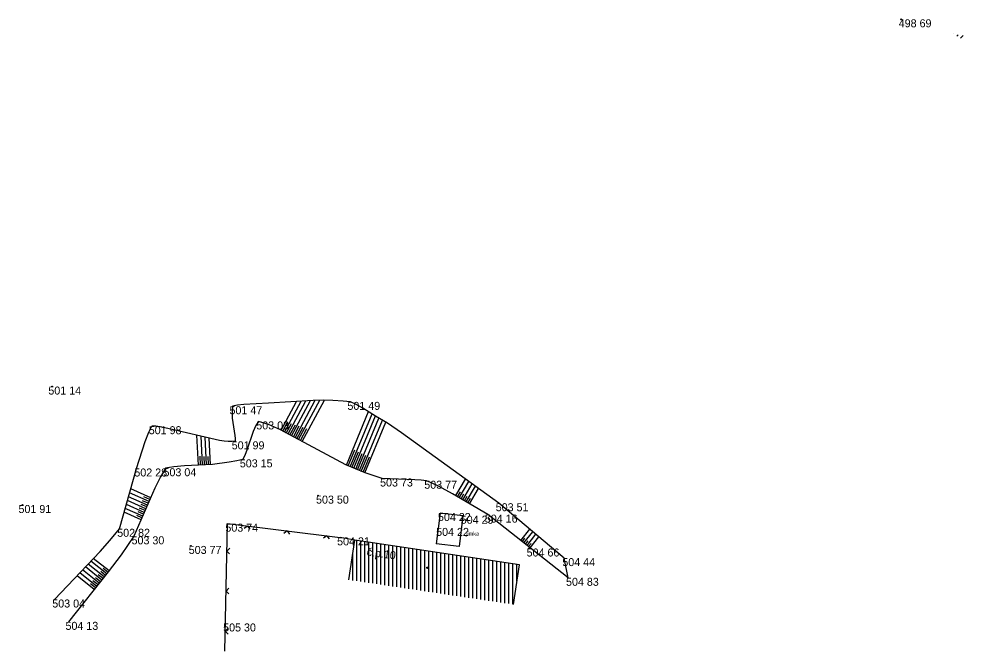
# Model space of a CAD drawing. Extents: x -554123 to -553118, y -1076825 to -1073672.
# Drawn here: x -553382.9 to -553265, y -1076824.9 to -1076745.9 of the extents above; entities that cross this region are included whole.
import ezdxf

# ---------------------------------------------------------------- set-up
doc = ezdxf.new("R2010")
doc.units = 0
for name, color, linetype in [('1', 7, 'Continuous'), ('12', 7, 'Continuous'), ('14', 7, 'Continuous'), ('18', 7, 'Continuous'), ('26', 7, 'Continuous'), ('27', 7, 'Continuous'), ('32', 7, 'Continuous'), ('47', 7, 'Continuous'), ('52', 7, 'Continuous'), ('54', 7, 'Continuous'), ('6', 7, 'Continuous')]:
    doc.layers.add(name, color=color, linetype=linetype)

# ---------------------------------------------------------------- blocks, each defined once
blk = doc.blocks.new('POINT_DISPLAY')
blk.add_line((0, 0), (0, 0))
blk = doc.blocks.new('T')
at = {"layer": '6'}
blk.add_circle((0, 0), 0.05, dxfattribs=at)
blk = doc.blocks.new('BZ')
at = {"layer": '47'}
blk.add_circle((0, 0), 0.0875, dxfattribs=at)

msp = doc.modelspace()

# ---------------------------------------------------------------- linework, layer by layer
at = {"layer": '12'}
for p, q in [((-553357.18, -1076824.88), (-553356.85, -1076808.96)), ((-553356.85, -1076808.96), (-553342.79, -1076810.67)), ((-553354.37, -1076809.26), (-553354.76, -1076809.57)), ((-553354.37, -1076809.26), (-553354.06, -1076809.66)), ((-553349.41, -1076809.86), (-553349.8, -1076810.17)), ((-553349.41, -1076809.86), (-553349.1, -1076810.26)), ((-553344.44, -1076810.47), (-553344.84, -1076810.78)), ((-553344.44, -1076810.47), (-553344.13, -1076810.86)), ((-553340.96, -1076811.02), (-553342.79, -1076810.67)), ((-553356.92, -1076812.38), (-553356.56, -1076812.03)), ((-553356.92, -1076812.38), (-553356.58, -1076812.74)), ((-553357.03, -1076817.38), (-553356.66, -1076817.03)), ((-553357.03, -1076817.38), (-553356.68, -1076817.74)), ((-553357.13, -1076822.38), (-553356.77, -1076822.03)), ((-553357.13, -1076822.38), (-553356.78, -1076822.74))]:
    msp.add_line(p, q, dxfattribs=at)
at = {"layer": '14'}
for p, q in [((-553341.7, -1076815.97), (-553340.96, -1076811.02)), ((-553320.4, -1076814.09), (-553340.96, -1076811.02)), ((-553321.14, -1076819.04), (-553320.4, -1076814.09))]:
    msp.add_line(p, q, dxfattribs=at)
at = {"layer": '18'}
for p, q in [((-553330.3, -1076807.63), (-553330.78, -1076811.47)), ((-553327.44, -1076807.97), (-553330.3, -1076807.63)), ((-553327.44, -1076807.97), (-553327.92, -1076811.81)), ((-553327.92, -1076811.81), (-553330.78, -1076811.47))]:
    msp.add_line(p, q, dxfattribs=at)
at = {"layer": '26'}
for p, q in [((-553348.84, -1076798), (-553346.48, -1076793.59)), ((-553348.4, -1076798.23), (-553345.9, -1076793.56)), ((-553347.96, -1076798.47), (-553345.32, -1076793.55)), ((-553347.52, -1076798.71), (-553344.75, -1076793.55)), ((-553350.16, -1076797.29), (-553348.23, -1076793.69)), ((-553349.72, -1076797.52), (-553347.65, -1076793.66)), ((-553349.28, -1076797.76), (-553347.06, -1076793.62)), ((-553341.99, -1076801.66), (-553339.22, -1076794.97)), ((-553341.53, -1076801.85), (-553338.79, -1076795.24)), ((-553341.07, -1076802.04), (-553338.36, -1076795.51)), ((-553340.61, -1076802.24), (-553337.93, -1076795.77)), ((-553349.94, -1076797.41), (-553349.34, -1076796.29)), ((-553349.5, -1076797.64), (-553348.86, -1076796.44)), ((-553349.06, -1076797.88), (-553348.37, -1076796.6)), ((-553348.62, -1076798.11), (-553347.89, -1076796.75)), ((-553348.18, -1076798.35), (-553347.41, -1076796.91)), ((-553347.74, -1076798.59), (-553346.93, -1076797.07)), ((-553340.15, -1076802.43), (-553337.5, -1076796.04)), ((-553339.68, -1076802.62), (-553337.07, -1076796.3)), ((-553360.48, -1076801.65), (-553360.66, -1076797.93)), ((-553359.98, -1076801.62), (-553360.15, -1076798.05)), ((-553359.48, -1076801.6), (-553359.64, -1076798.17)), ((-553358.98, -1076801.57), (-553359.14, -1076798.29)), ((-553360.23, -1076801.63), (-553360.28, -1076800.54)), ((-553359.73, -1076801.61), (-553359.78, -1076800.56)), ((-553359.23, -1076801.59), (-553359.28, -1076800.58)), ((-553341.76, -1076801.76), (-553340.94, -1076799.76)), ((-553341.3, -1076801.95), (-553340.48, -1076799.98)), ((-553340.84, -1076802.14), (-553340.03, -1076800.19)), ((-553340.38, -1076802.33), (-553339.58, -1076800.4)), ((-553339.91, -1076802.52), (-553339.12, -1076800.62)), ((-553328.33, -1076805.46), (-553327.11, -1076803.41)), ((-553327.9, -1076805.72), (-553326.7, -1076803.7)), ((-553327.47, -1076805.97), (-553326.3, -1076804)), ((-553366.64, -1076806.18), (-553369.07, -1076805.11)), ((-553366.44, -1076805.72), (-553368.93, -1076804.63)), ((-553328.11, -1076805.59), (-553327.75, -1076804.98)), ((-553327.68, -1076805.85), (-553327.33, -1076805.25)), ((-553327.04, -1076806.23), (-553325.89, -1076804.29)), ((-553326.61, -1076806.48), (-553325.48, -1076804.59)), ((-553367.24, -1076807.55), (-553369.48, -1076806.57)), ((-553367.04, -1076807.09), (-553369.34, -1076806.08)), ((-553366.84, -1076806.64), (-553369.2, -1076805.6)), ((-553366.94, -1076806.86), (-553367.64, -1076806.56)), ((-553366.74, -1076806.41), (-553367.46, -1076806.09)), ((-553366.54, -1076805.95), (-553367.28, -1076805.63)), ((-553327.25, -1076806.1), (-553326.9, -1076805.51)), ((-553326.82, -1076806.36), (-553326.48, -1076805.78)), ((-553367.64, -1076808.47), (-553369.76, -1076807.54)), ((-553367.44, -1076808.01), (-553369.62, -1076807.06)), ((-553367.34, -1076807.78), (-553368, -1076807.49)), ((-553367.14, -1076807.32), (-553367.82, -1076807.02)), ((-553367.54, -1076808.24), (-553368.19, -1076807.96)), ((-553320.23, -1076811.06), (-553319.11, -1076809.64)), ((-553319.83, -1076811.37), (-553318.72, -1076809.96)), ((-553320.03, -1076811.22), (-553319.7, -1076810.79)), ((-553319.64, -1076811.53), (-553319.31, -1076811.11)), ((-553319.44, -1076811.68), (-553318.34, -1076810.29)), ((-553319.05, -1076811.99), (-553317.96, -1076810.61)), ((-553319.24, -1076811.83), (-553318.92, -1076811.42)), ((-553371.92, -1076815.23), (-553373.91, -1076813.64)), ((-553371.61, -1076814.84), (-553373.62, -1076813.33)), ((-553372.86, -1076816.4), (-553374.95, -1076814.73)), ((-553372.55, -1076816.01), (-553374.6, -1076814.37)), ((-553372.23, -1076815.62), (-553374.26, -1076814)), ((-553371.76, -1076815.04), (-553372.36, -1076814.56)), ((-553373.48, -1076817.18), (-553375.64, -1076815.46)), ((-553373.17, -1076816.79), (-553375.3, -1076815.09)), ((-553372.7, -1076816.21), (-553373.32, -1076815.71)), ((-553372.39, -1076815.82), (-553373, -1076815.33)), ((-553372.08, -1076815.43), (-553372.68, -1076814.95)), ((-553373.33, -1076816.99), (-553373.97, -1076816.48)), ((-553373.01, -1076816.6), (-553373.65, -1076816.09))]:
    msp.add_line(p, q, dxfattribs=at)
at = {"layer": '27'}
for p, q in [((-553370.34, -1076809.6), (-553368.2, -1076802.07)), ((-553314.79, -1076813.26), (-553322.97, -1076806.41)), ((-553314.31, -1076815.72), (-553324.33, -1076807.83)), ((-553314.31, -1076815.72), (-553314.79, -1076813.26))]:
    msp.add_line(p, q, dxfattribs=at)
for points in [[(-553341.49, -1076793.75), (-553342.41, -1076793.65), (-553343.69, -1076793.57), (-553344.88, -1076793.54), (-553346.16, -1076793.57), (-553351.74, -1076793.9), (-553354.82, -1076794.09), (-553355.6, -1076794.17), (-553356.23, -1076794.3)], [(-553356.23, -1076794.3), (-553356.28, -1076794.9), (-553356.25, -1076795.78), (-553355.94, -1076797.95), (-553355.91, -1076798.33), (-553355.91, -1076798.68)], [(-553322.97, -1076806.41), (-553335.12, -1076797.61), (-553336.86, -1076796.43), (-553338.35, -1076795.52), (-553339.94, -1076794.53), (-553340.76, -1076794.09), (-553341.49, -1076793.75)], [(-553368.2, -1076802.07), (-553367.12, -1076798.71), (-553366.67, -1076797.52), (-553366.47, -1076797.12), (-553366.28, -1076796.79)], [(-553355.91, -1076798.68), (-553356.29, -1076798.7), (-553356.76, -1076798.7), (-553357.26, -1076798.67), (-553357.84, -1076798.59), (-553364.28, -1076797.08), (-553365.27, -1076796.87), (-553365.79, -1076796.8), (-553366.28, -1076796.79)], [(-553352.97, -1076796.19), (-553353.29, -1076796.72), (-553353.63, -1076797.44), (-553354.44, -1076799.78), (-553354.65, -1076800.33), (-553354.93, -1076800.93)], [(-553337.52, -1076803.32), (-553339.66, -1076802.63), (-553342.08, -1076801.62), (-553350.22, -1076797.26), (-553351.72, -1076796.58), (-553352.97, -1076796.19)], [(-553354.93, -1076800.93), (-553355.68, -1076801.1), (-553356.65, -1076801.28), (-553358.7, -1076801.56), (-553362.2, -1076801.73), (-553363.53, -1076801.86), (-553364.08, -1076801.94), (-553364.57, -1076802.04)], [(-553364.57, -1076802.04), (-553364.9, -1076802.56), (-553365.22, -1076803.13), (-553365.91, -1076804.53), (-553368.55, -1076810.54)], [(-553332, -1076803.6), (-553332.65, -1076803.53), (-553333.47, -1076803.48), (-553337.52, -1076803.32)], [(-553324.33, -1076807.83), (-553328.74, -1076805.22), (-553330.48, -1076804.29), (-553331.29, -1076803.9), (-553332, -1076803.6)], [(-553378.46, -1076818.43), (-553372.77, -1076812.43), (-553371.53, -1076811.06), (-553370.34, -1076809.6)], [(-553368.55, -1076810.54), (-553370.14, -1076812.87), (-553371.73, -1076814.99), (-553376.71, -1076821.22)]]:
    msp.add_lwpolyline(points, dxfattribs=at)
at = {"layer": '32'}
for p, q in [((-553265.76, -1076748.08), (-553265.59, -1076747.91)), ((-553265.32, -1076748.35), (-553264.98, -1076748.01)), ((-553340.7, -1076816.11), (-553340.7, -1076811.06)), ((-553340.2, -1076816.19), (-553340.2, -1076811.13)), ((-553339.7, -1076816.26), (-553339.7, -1076811.21)), ((-553339.2, -1076816.34), (-553339.2, -1076811.28)), ((-553338.7, -1076816.41), (-553338.7, -1076811.36)), ((-553338.2, -1076816.49), (-553338.2, -1076811.43)), ((-553337.7, -1076816.56), (-553337.7, -1076811.51)), ((-553337.2, -1076816.64), (-553337.2, -1076811.58)), ((-553336.7, -1076816.71), (-553336.7, -1076811.66)), ((-553336.2, -1076816.79), (-553336.2, -1076811.73)), ((-553335.7, -1076816.86), (-553335.7, -1076811.81)), ((-553335.2, -1076816.94), (-553335.2, -1076811.88)), ((-553334.7, -1076817.01), (-553334.7, -1076811.96)), ((-553334.2, -1076817.08), (-553334.2, -1076812.03)), ((-553333.7, -1076817.16), (-553333.7, -1076812.1)), ((-553333.2, -1076817.23), (-553333.2, -1076812.18)), ((-553332.7, -1076817.31), (-553332.7, -1076812.25)), ((-553332.2, -1076817.38), (-553332.2, -1076812.33)), ((-553331.7, -1076817.46), (-553331.7, -1076812.4)), ((-553331.2, -1076817.53), (-553331.2, -1076812.48)), ((-553341.2, -1076816.04), (-553341.2, -1076812.61)), ((-553330.7, -1076817.61), (-553330.7, -1076812.55)), ((-553330.2, -1076817.68), (-553330.2, -1076812.63)), ((-553329.7, -1076817.76), (-553329.7, -1076812.7)), ((-553329.2, -1076817.83), (-553329.2, -1076812.78)), ((-553328.7, -1076817.91), (-553328.7, -1076812.85)), ((-553328.2, -1076817.98), (-553328.2, -1076812.93)), ((-553327.7, -1076818.06), (-553327.7, -1076813)), ((-553327.2, -1076818.13), (-553327.2, -1076813.07)), ((-553326.7, -1076818.21), (-553326.7, -1076813.15)), ((-553326.2, -1076818.28), (-553326.2, -1076813.22)), ((-553325.7, -1076818.35), (-553325.7, -1076813.3)), ((-553325.2, -1076818.43), (-553325.2, -1076813.37)), ((-553324.7, -1076818.5), (-553324.7, -1076813.45)), ((-553324.2, -1076818.58), (-553324.2, -1076813.52)), ((-553323.7, -1076818.65), (-553323.7, -1076813.6)), ((-553323.2, -1076818.73), (-553323.2, -1076813.67)), ((-553322.7, -1076818.8), (-553322.7, -1076813.75)), ((-553322.2, -1076818.88), (-553322.2, -1076813.82)), ((-553321.7, -1076818.95), (-553321.7, -1076813.9)), ((-553321.2, -1076819.03), (-553321.2, -1076813.97)), ((-553320.7, -1076816.09), (-553320.7, -1076814.05))]:
    msp.add_line(p, q, dxfattribs=at)

# ---------------------------------------------------------------- block references
at = {"layer": '1'}
for p in [(-553272.72, -1076745.98), (-553378.74, -1076791.84), (-553356.23, -1076794.3), (-553341.49, -1076793.75), (-553366.28, -1076796.79), (-553352.97, -1076796.19), (-553355.91, -1076798.68), (-553354.93, -1076800.93), (-553368.2, -1076802.07), (-553364.57, -1076802.04), (-553337.52, -1076803.32), (-553332, -1076803.6), (-553345.51, -1076805.46), (-553322.97, -1076806.41), (-553382.45, -1076806.63), (-553330.3, -1076807.63), (-553327.44, -1076807.97), (-553324.33, -1076807.83), (-553370.34, -1076809.6), (-553356.85, -1076808.96), (-553330.53, -1076809.49), (-553368.55, -1076810.54), (-553342.79, -1076810.67), (-553340.96, -1076811.02), (-553361.42, -1076811.74), (-553319.2, -1076812.06), (-553314.79, -1076813.26), (-553320.4, -1076814.09), (-553314.31, -1076815.72), (-553378.46, -1076818.43), (-553376.71, -1076821.22), (-553357.11, -1076821.42)]:
    msp.add_blockref('POINT_DISPLAY', p, dxfattribs=at)
at = {"layer": '32'}
msp.add_blockref('POINT_DISPLAY', (-553266.2, -1076747.81), dxfattribs=at)
at = {"layer": '47'}
msp.add_blockref('BZ', (-553331.88, -1076814.47), dxfattribs=at)
at = {"layer": '6'}
for p in [(-553272.72, -1076745.98), (-553378.74, -1076791.84), (-553382.45, -1076806.63), (-553345.51, -1076805.46), (-553361.42, -1076811.74), (-553319.2, -1076812.06)]:
    msp.add_blockref('T', p, dxfattribs=at)

# ---------------------------------------------------------------- texts
at = {"layer": '52'}
msp.add_text('jímka', height=0.5, dxfattribs=at).set_placement((-553327.07, -1076810.46))
at = {"layer": '54'}
msp.add_text('č.p.10', height=1, rotation=352.3891, dxfattribs=at).set_placement((-553339.51, -1076812.95))
at = {"layer": '6'}
for s, p in [('498 69 ', (-553273.02, -1076746.98)), ('501 14 ', (-553379.22, -1076792.84)), ('501 47 ', (-553356.6, -1076795.3)), ('501 49 ', (-553341.87, -1076794.75)), ('501 98 ', (-553366.68, -1076797.79)), ('503 03 ', (-553353.25, -1076797.19)), ('501 99 ', (-553356.32, -1076799.68)), ('503 15 ', (-553355.31, -1076801.93)), ('502 28 ', (-553368.48, -1076803.07)), ('503 04 ', (-553364.84, -1076803.04)), ('503 73 ', (-553337.79, -1076804.32)), ('503 77 ', (-553332.27, -1076804.6)), ('503 50 ', (-553345.79, -1076806.46)), ('503 51 ', (-553323.35, -1076807.41)), ('501 91 ', (-553382.95, -1076807.63)), ('504 22 ', (-553330.56, -1076808.63)), ('504 29 ', (-553327.72, -1076808.97)), ('504 16 ', (-553324.71, -1076808.83)), ('502 82 ', (-553370.62, -1076810.6)), ('503 74 ', (-553357.11, -1076809.96)), ('504 22 ', (-553330.79, -1076810.49)), ('503 30 ', (-553368.83, -1076811.54)), ('504 21 ', (-553343.16, -1076811.67)), ('503 77 ', (-553361.69, -1076812.74)), ('504 66 ', (-553319.49, -1076813.06)), ('504 44 ', (-553315.03, -1076814.26)), ('504 83 ', (-553314.57, -1076816.72)), ('503 04 ', (-553378.73, -1076819.43)), ('504 13 ', (-553377.08, -1076822.22)), ('505 30 ', (-553357.39, -1076822.42))]:
    msp.add_text(s, height=1, dxfattribs=at).set_placement(p)

doc.saveas('drawing.dxf')
